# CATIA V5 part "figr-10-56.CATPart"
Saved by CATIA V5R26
Part number: Part1
Bounding box of the stored display mesh (mm): x -101.896 to 127.212, y -67.72 to 67.298, z 0 to 0
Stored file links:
  D:\_Deepak\CATIA\CATIA V5 2015 Parts Files\Part files\Partfiles\c10_catia_v5_6r2016_prt\figr-10-56.CATPart
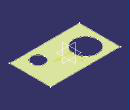
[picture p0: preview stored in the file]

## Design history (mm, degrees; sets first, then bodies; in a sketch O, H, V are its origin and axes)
Body1 (main body)
  Sketch1 on xy-plane, origin (0, 0, 0), H (1, 0, 0), V (0, 1, 0)
    line L1 (-101.8963, 67.298) -> (127.2122, 67.298)
    line L2 (127.2122, 67.298) -> (127.2122, -67.7199)
    line L3 (127.2122, -67.7199) -> (-101.8963, -67.7199)
    line L4 (-101.8963, -67.7199) -> (-101.8963, 67.298)
    horizontal: L1 H, L3 H
    vertical: L2 V, L4 V
  Sketch2 on xy-plane, origin (0, 0, 0), H (1, 0, 0), V (0, 1, 0)
    circle A1 centre (-45.2964, 9.2296) radius 39.3004
    circle A2 centre (71.0804, -29.9585) radius 20.9926
  Fill1: Boundary Sketch1, InnerBoundaries {fillinnerboundary Boundaries Sketch2}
